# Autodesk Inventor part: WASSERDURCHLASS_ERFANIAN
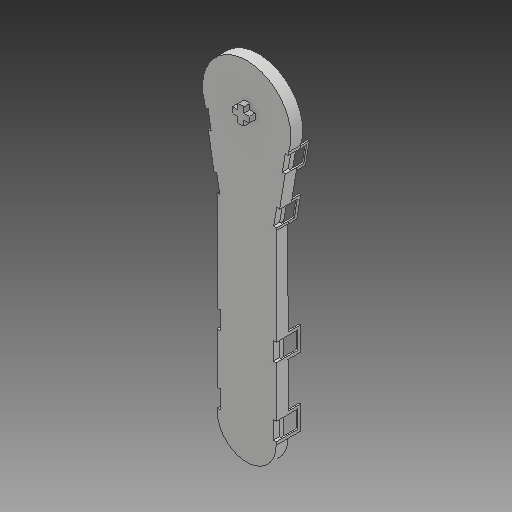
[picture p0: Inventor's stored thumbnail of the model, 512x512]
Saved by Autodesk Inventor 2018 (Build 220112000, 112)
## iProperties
Created: 2019-01
Part Number: WASSERDURCHLASS_ERFANIAN
Material: Generisch
Document SubType Name: Modeling
Designer: zand
Density: 1 g/cm^3
Appearance: Vorgabe
Author: zand
Revision Number: 12LAST_VERSION
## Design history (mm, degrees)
feature "Basis1"
node "Volumenkörper1"
